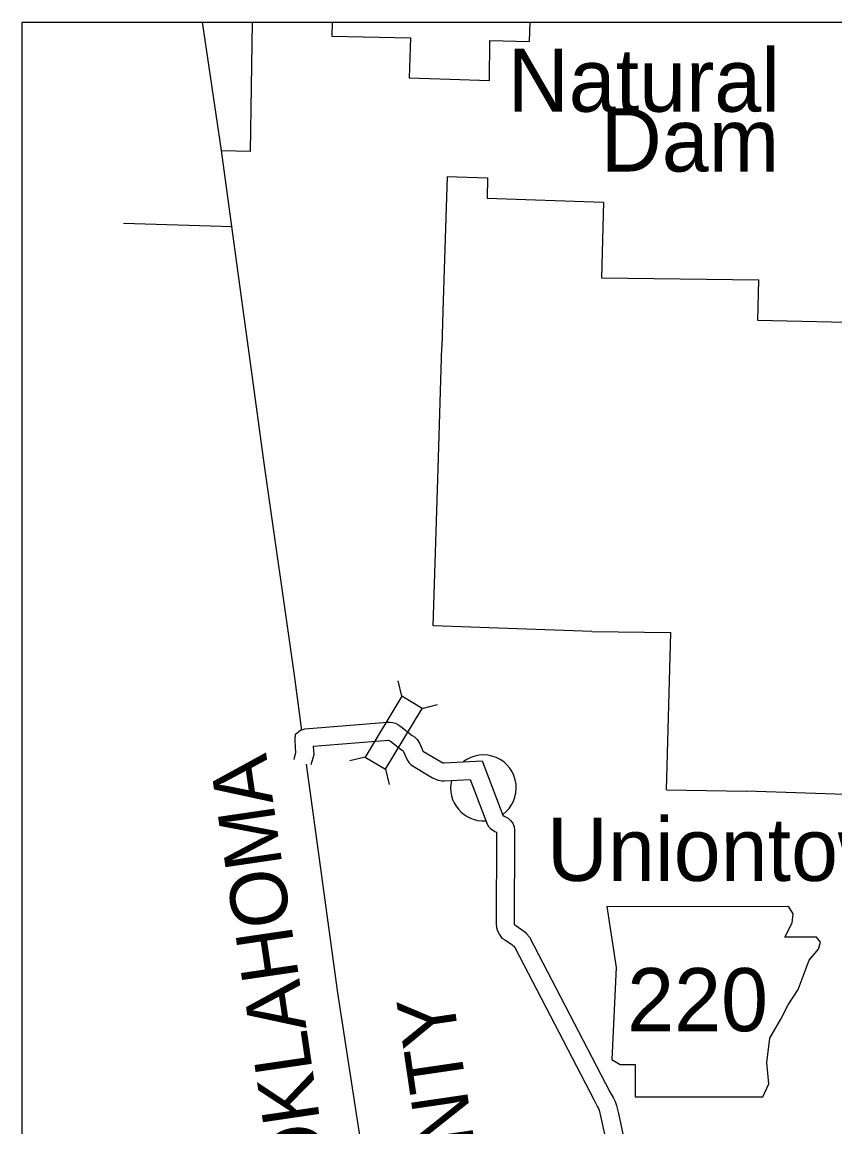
# Model space of a CAD drawing. Extents: x 535214 to 694517, y 381272 to 484355.
# Drawn here: x 535214 to 542010, y 470990 to 480223 of the extents above; entities that cross this region are included whole.
import ezdxf

# ---------------------------------------------------------------- set-up
doc = ezdxf.new("R2010")
doc.units = 0
for name, color, linetype in [('1', 7, 'Continuous'), ('21', 7, 'Continuous'), ('Level 1', 7, 'Continuous'), ('Level 10', 7, 'Continuous'), ('Level 2', 7, 'Continuous'), ('Level 20', 7, 'Continuous'), ('Level 21', 7, 'Continuous'), ('Level 24', 7, 'Continuous'), ('Level 8', 7, 'Continuous')]:
    doc.layers.add(name, color=color, linetype=linetype)

msp = doc.modelspace()

# ---------------------------------------------------------------- linework, layer by layer
at = {"layer": '1'}
msp.add_lwpolyline([(535213.7, 480223.3), (566227, 480223.3), (566227, 448175.2), (535213.7, 448175.2)], close=True, dxfattribs=at)
at = {"layer": 'Level 1'}
for points in [[(536718.8, 480223.3), (536877.1, 479150.2), (537057.7, 477841.1), (537105, 477497.3)], [(537105, 477497.3), (537233.7, 476536.2), (537487.4, 474766), (537550.2, 474303.5)], [(537588.6, 474021.1), (537668.3, 473433.7), (537851.7, 472111.5), (538054, 470793.4), (538186.9, 469927.4), (538370.8, 468605.7), (538556.6, 467284.5), (538690.8, 466131.4)]]:
    msp.add_lwpolyline(points, dxfattribs=at)
at = {"layer": 'Level 10'}
for points in [[(537487.3, 474060.7), (537503.8, 474117.9), (537499.5, 474164.8), (537495.7, 474224.6), (537500.1, 474272.6), (537542, 474305.4), (537576.3, 474317.2), (538269.5, 474373), (538290.9, 474373.2), (538309.8, 474370.2), (538335.3, 474363.4), (538354, 474351.8), (538379.2, 474336.5), (538475.8, 474262.1), (538494.2, 474249), (538517.5, 474227.9), (538536.3, 474197.5), (538557.5, 474147.1), (538565, 474130.3), (538569.5, 474126.4), (538716.8, 474040.8), (538732.4, 474033.2), (538735.8, 474032.8), (538742.3, 474032.3), (539060.8, 474050.2), (539233.4, 473594.9), (539244.1, 473588.2), (539278.2, 473569.1), (539298.1, 473551.8), (539316.5, 473528), (539327.5, 473497), (539330.5, 473470.1), (539330.8, 473432.7), (539327.1, 472694.8), (539328.1, 472685), (539329.9, 472680.6), (539334.6, 472677.8), (539398.8, 472634.5), (539420.3, 472616), (539434.6, 472601.2), (539457.4, 472575.2), (540128.7, 471283.8), (540157.9, 471229.9), (540172.1, 471203.2), (540183.4, 471169.2), (540198.8, 471101), (540251.3, 470865.3)], [(537631.4, 474019.1), (537655.7, 474103.3), (537649.4, 474172.6), (538276.1, 474223.1), (538277, 474223.1), (538294.4, 474212.5), (538386.6, 474141.4), (538400.2, 474131.8), (538401, 474131), (538402.5, 474128.6), (538419.9, 474087.3), (538433.7, 474056.5), (538447.9, 474034.4), (538465, 474018.4), (538482.5, 474003.5), (538645.9, 473908.5), (538670.1, 473896.6), (538693.4, 473886.7), (538721.9, 473883.4), (538741.4, 473882), (538959.5, 473894.3), (539098.2, 473528.5), (539111.5, 473504.1), (539129.5, 473483.1), (539167.3, 473459.3), (539180.6, 473451.8), (539180.8, 473432.5), (539177, 472687.2), (539180.3, 472657.1), (539185.4, 472638), (539193.8, 472616.6), (539204.9, 472596.5), (539225.3, 472568.1), (539254.5, 472550.9), (539307.7, 472515), (539317.3, 472506.8), (539324.1, 472499.7), (539332.6, 472490), (539996.2, 471213.5), (540025.7, 471158.9), (540033.8, 471143.8), (540038.8, 471128.9), (540052.4, 471068.3), (540103.2, 470839.8)]]:
    msp.add_lwpolyline(points, dxfattribs=at)
at = {"layer": 'Level 2'}
msp.add_line((536968.9, 478512.2), (536061.5, 478541), dxfattribs=at)
at = {"layer": 'Level 20'}
for p, q in [((538389.7, 474589.6), (538358.1, 474717.7)), ((538559.2, 474487.2), (538687.3, 474518.8)), ((538082.5, 474081.2), (537954.3, 474049.6)), ((538251.9, 473978.8), (538283.5, 473850.6))]:
    msp.add_line(p, q, dxfattribs=at)
msp.add_lwpolyline([(538251.9, 473978.8), (538559.2, 474487.2), (538389.7, 474589.6), (538082.5, 474081.2)], close=True, dxfattribs=at)
at = {"layer": 'Level 21'}
msp.add_lwpolyline([(540103.3, 472830.6), (540179.4, 472323), (540145.6, 471553.3), (540213.3, 471511), (540340.2, 471511), (540340.2, 471240.3), (541406, 471240.3), (541456.7, 471350.3), (541439.8, 471527.9), (541465.2, 471730.9), (541558.2, 471891.6), (541617.5, 472010.1), (541702, 472137), (541752.8, 472272.3), (541795.1, 472382.3), (541871.2, 472475.3), (541888.1, 472534.5), (541854.3, 472576.8), (541592.1, 472576.8), (541651.3, 472695.2), (541659.7, 472771.4), (541624.7, 472829.8)], close=True, dxfattribs=at)
at = {"layer": 'Level 24'}
for start, end in [(306.06576, 127.8028), (167.05556, 273.85248)]:
    msp.add_arc((539070.6, 473823.1), 275, start, end, dxfattribs=at)
at = {"layer": 'Level 8'}
for points in [[(537123.3, 479143), (537141.1, 480223.3)], [(537806.7, 480223.3), (537803.1, 480104.3), (538461.4, 480090.8), (538449.3, 479757.6), (538790, 479746), (539122.1, 479735.2), (539125.3, 480070.8), (539455.9, 480060.6), (539460.5, 480223.3)], [(537123.3, 479143), (536877.4, 479147.6)], [(538768, 478933.7), (538732.8, 477810.6), (538723.5, 477506.9)], [(538768, 478933.7), (539106, 478920.9), (539101.7, 478751.8), (540074.8, 478718.6)], [(540074.8, 478718.6), (540057.3, 478085.2)], [(540057.3, 478085.2), (541373.3, 478069.2)], [(542349.1, 477706.1), (541365.7, 477729.6), (541373.3, 478069.2)], [(538651.9, 475176.3), (538692.3, 476492.2), (538723.5, 477506.9)], [(539977.5, 475131.4), (538651.9, 475176.3)], [(539977.5, 475131.4), (540637.4, 475121.7)], [(540602.3, 473808.2), (540637.4, 475121.7)], [(540602.3, 473808.2), (541271.4, 473794.4)], [(543247.9, 473734.3), (542588.8, 473750.2), (541271.4, 473794.4)]]:
    msp.add_lwpolyline(points, dxfattribs=at)

# ---------------------------------------------------------------- texts
at = {"layer": '21'}
for s, p in [('SEQUOYAH COUNTY, OKLAHOMA', (538769, 463815.7)), ('CRAWFORD COUNTY', (539772.8, 465585))]:
    msp.add_text(s, height=475.199, rotation=98.36935, dxfattribs=at).set_placement(p)
at = {"layer": 'Level 21'}
msp.add_text('220', height=528, dxfattribs=at).set_placement((540272.5, 471789.1))
at = {"layer": 'Level 24'}
for s, p in [('Natural', (539274.2, 479474.1)), ('Dam', (540052.1, 478974.4)), ('Uniontown', (539602.1, 473045.5))]:
    msp.add_text(s, height=528, dxfattribs=at).set_placement(p)

doc.saveas('drawing.dxf')
